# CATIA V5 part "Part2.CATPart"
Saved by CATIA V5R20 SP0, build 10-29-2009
Part number: Part2
Bounding box of the stored display mesh (mm): x -79.921 to 79.921, y -80 to 119.816, z 0 to 5
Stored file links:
  C:\Users\Lenovo\Desktop\学习\Part2.CATPart
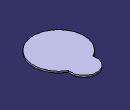
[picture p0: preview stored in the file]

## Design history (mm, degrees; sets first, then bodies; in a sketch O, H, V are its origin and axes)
Body1 (main body)
  Sketch1 on xy-plane, origin (0, 0, 0), H (1, 0, 0), V (0, 1, 0)
    arc A1 centre (0, 0) radius 80 from (-38.7298, 70) to (38.7298, 70) ccw
    arc A2 centre (0, 80) radius 40 from (38.7298, 70) to (-38.7298, 70) ccw
    point P1 (0, 80)
    radius A1 = 80
    radius A2 = 40
    coincidence: P1 V, P1 A1
  Pad1: profile Sketch1, direction (0, 0, 1), length 5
